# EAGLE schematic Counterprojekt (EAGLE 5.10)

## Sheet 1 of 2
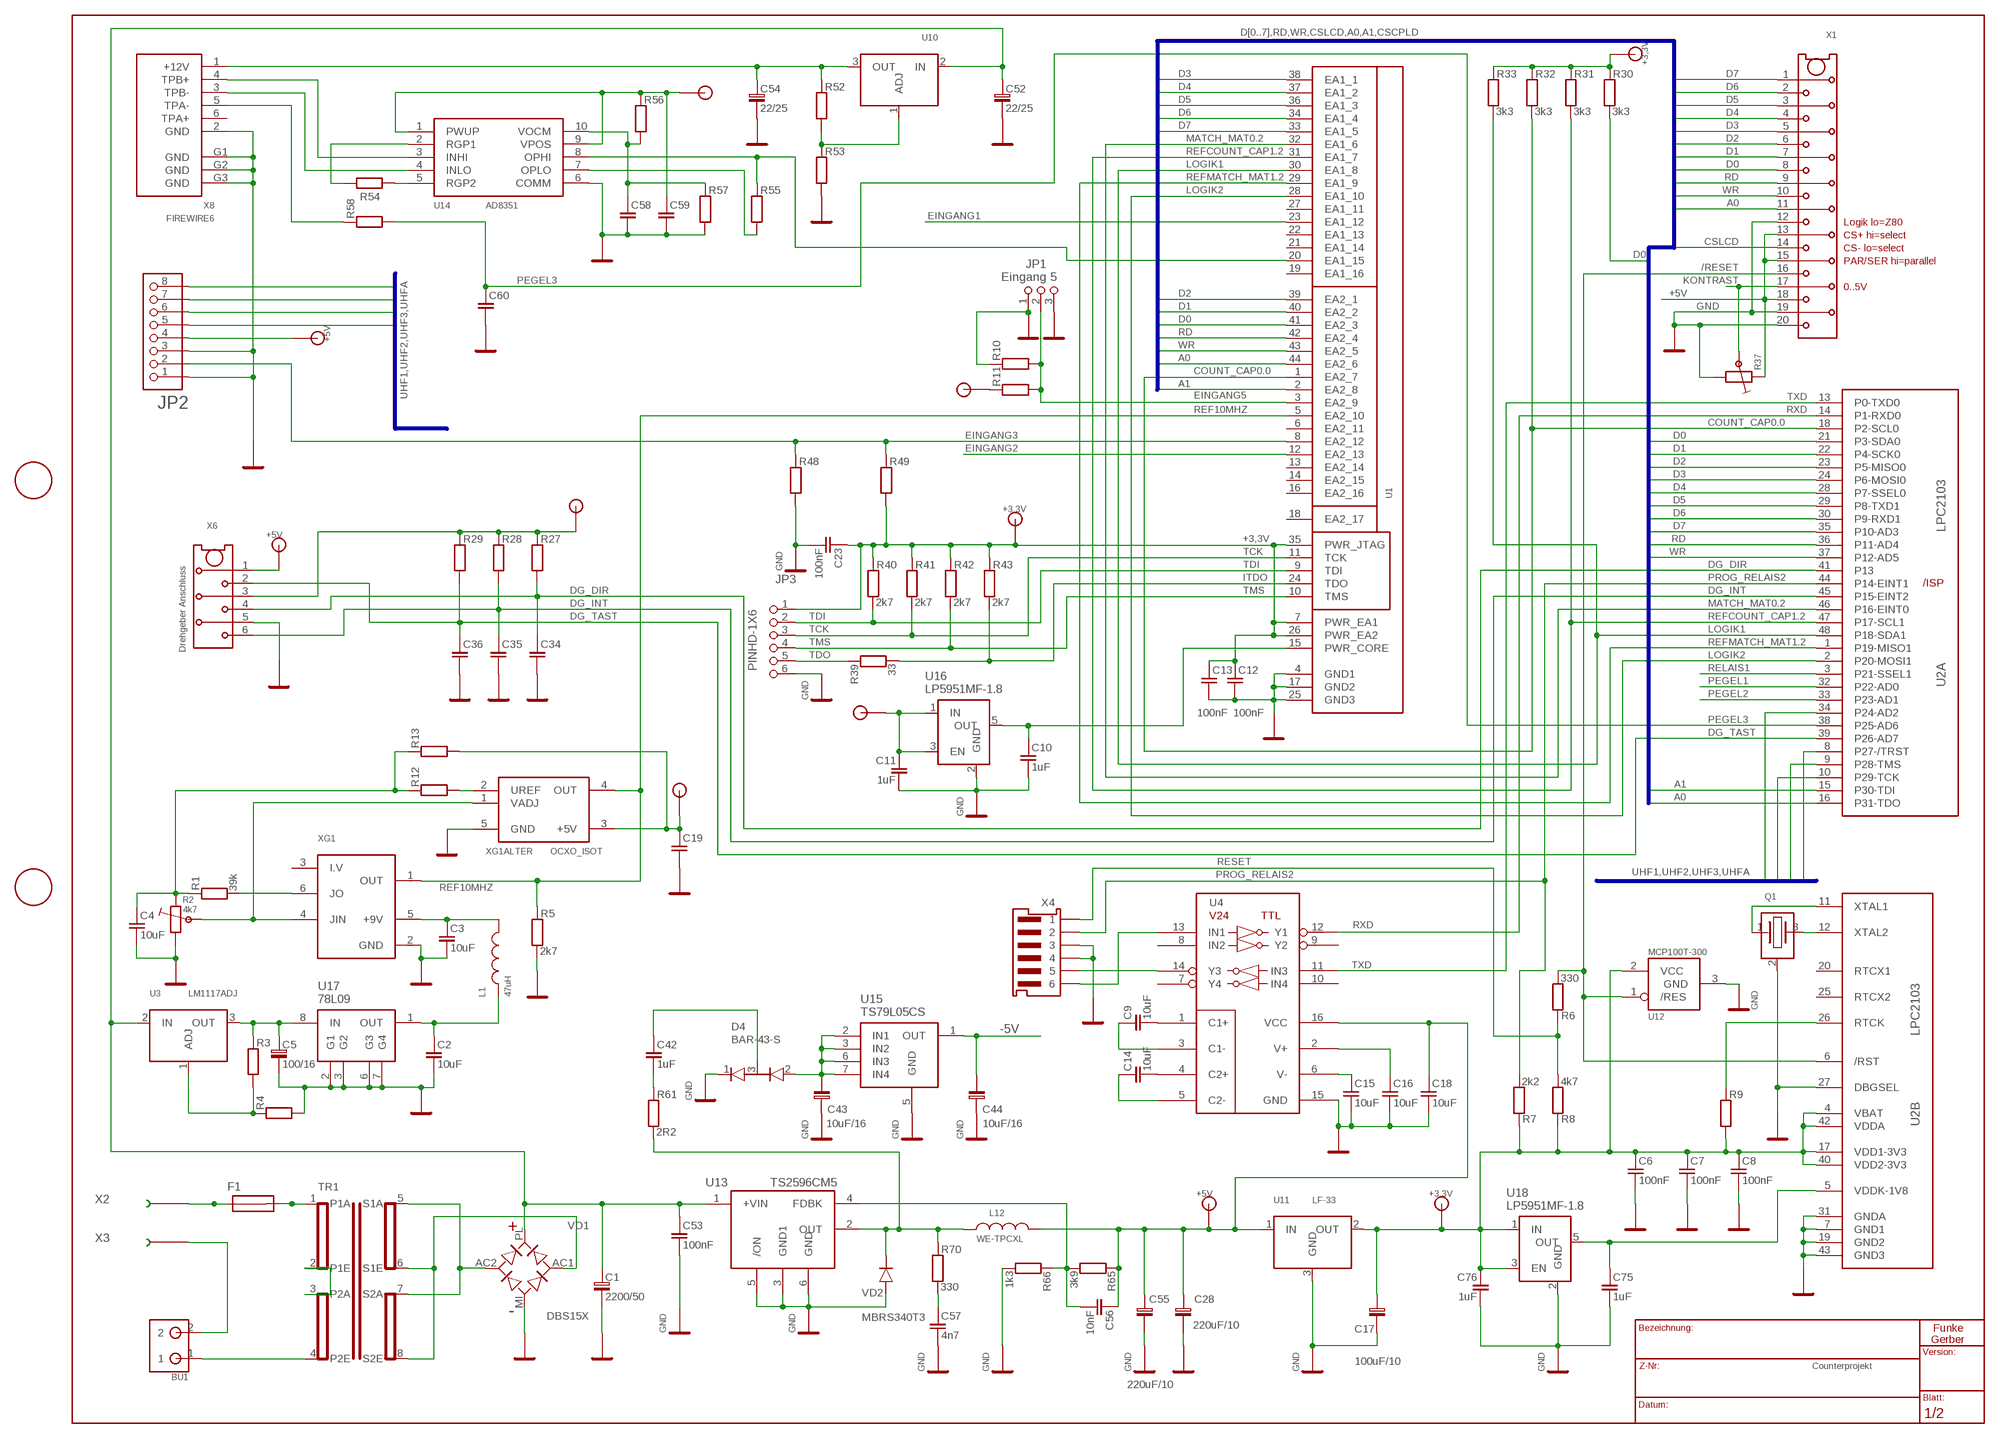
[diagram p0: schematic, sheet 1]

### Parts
BU1  NETZ_BU  [NETZ_BU]
C1  2200/50  [D25-RM10]
C2  10uF  SMD-1206  [SOT-1206]
C3  10uF  SMD-1206  [SOT-1206]
C4  10uF  SMD-1206  [SOT-1206]
C5  100/16  TAJ_D  [TAJ_D]
C6  100nF  SMD-0603  [SOT-0603]
C7  100nF  SMD-0603  [SOT-0603]
C8  100nF  SMD-0603  [SOT-0603]
C9  10uF  SMD-1206  [SOT-1206]
C10  1uF  SMD-0805@3  [SOT-0805@2]
C11  1uF  SMD-0805@3  [SOT-0805@2]
C12  100nF  SMD-0603  [SOT-0603]
C13  100nF  SMD-0603  [SOT-0603]
C14  10uF  SMD-1206  [SOT-1206]
C15  10uF  SMD-1206  [SOT-1206]
C16  10uF  SMD-1206  [SOT-1206]
C17  100uF/10  TAJ_D  [TAJ_D]
C18  10uF  SMD-1206  [SOT-1206]
C19  SMD-0805  [SOT-0805]
C23  100nF  SMD-1206@3  [SOT-0603]
C28  220uF/10  TAJ_D  [TAJ_D]
C34  SMD-0603  [SOT-0603]
C35  SMD-0603  [SOT-0603]
C36  SMD-0603  [SOT-0603]
C42  1uF  SMD-1206  [SOT-1206]
C43  10uF/16  TAJ_B  [TAJ_B]
C44  10uF/16  TAJ_B  [TAJ_B]
C52  22/25  TAJ_D  [TAJ_D]
C53  100nF  SMD-1206  [SOT-1206]
C54  22/25  TAJ_D  [TAJ_D]
C55  220uF/10  TAJ_D  [TAJ_D]
C56  10nF  SMD-0603  [SOT-0603]
C57  4n7  SMD-1206  [SOT-1206]
C58  SMD-0603  [SOT-0603]
C59  SMD-0603  [SOT-0603]
C60  SMD-0603  [SOT-0603]
C75  1uF  SMD-0805@3  [SOT-0805@2]
C76  1uF  SMD-0805@3  [SOT-0805@2]
D4  BAR-43-S  [SOT-23]
F1  FUS-HALT  [FUS-HALT]
JP1  Eingang 5  PINHD-1X3  [1X03]
JP2  PINHD-1X8  [1X08]
JP3  PINHD-1X6  [1X06]
L1  47uH  SMD-1210  [SMD-1210]
L12  WE-TPCXL  [WE-TPCXL]
Q1  ZTTCV  [ZTTCV]
R1  39k  SMD-0805  [SMD-0805]
R2  4k7  RFT10L  [RFT-LIEG]
R3  SMD-0805  [SMD-0805]
R4  SMD-0805  [SMD-0805]
R5  2k7  SMD-0805  [SMD-0805]
R6  330  SMD-0603  [SMD-0603]
R7  2k2  SMD-0603  [SMD-0603]
R8  4k7  SMD-0603  [SMD-0603]
R9  SMD-0603  [SMD-0603]
R10  SMD-0603  [SMD-0603]
R11  SMD-0603  [SMD-0603]
R12  SMD-0805  [SMD-0805]
R13  SMD-0805  [SMD-0805]
R27  SMD-0603  [SMD-0603]
R28  SMD-0603  [SMD-0603]
R29  SMD-0603  [SMD-0603]
R30  3k3  SMD-0603  [SMD-0603]
R31  3k3  SMD-0603  [SMD-0603]
R32  3k3  SMD-0603  [SMD-0603]
R33  3k3  SMD-0603  [SMD-0603]
R37  RFT10L  [RFT-LIEG]
R39  33  SMD-1206  [SMD-0603@1]
R40  2k7  SMD-1206  [SMD-0603@1]
R41  2k7  SMD-1206  [SMD-0603@1]
R42  2k7  SMD-1206  [SMD-0603@1]
R43  2k7  SMD-1206  [SMD-0603@1]
R48  SMD-0603  [SMD-0603]
R49  SMD-0603  [SMD-0603]
R52  SMD-0805  [SMD-0805]
R53  SMD-0805  [SMD-0805]
R54  SMD-0603  [SMD-0603]
R55  SMD-0603  [SMD-0603]
R56  SMD-0603  [SMD-0603]
R57  SMD-0603  [SMD-0603]
R58  SMD-0603  [SMD-0603]
R61  2R2  SMD-0805@3  [SMD-1206]
R65  3k9  SMD-0603@2  [SMD-0603@2]
R66  1k3  SMD-0603@2  [SMD-0603@2]
R70  330  SMD-1206  [SMD-1206]
TR1  HAHN-6VA  [HAHN-6VA]
U1  32A-VQ44  [VQ44]
U2  LPC2103  LPC210X  [LQFP48]
U3  LM1117ADJ  LM1117  [DPAK]
U4  MAX-232CWE  [SO-16W]
U10  LM1117  [DPAK]
U11  LF-33  LF-XXX  [DPAK]
U12  MCP100T-300  TC1275  [SOT23]
U13  TS2596CM5  [TO263-5L]
U14  AD8351  [RM-10]
U15  TS79L05CS  LM79SMDX  [SO-8]
U16  LP5951MF-1.8  LP5951MF  [SOT-23-5]
U17  78L09  LM78SMDX  [SO-8]
U18  LP5951MF-1.8  LP5951MF  [SOT-23-5]
VD1  DBS15X  [DBS15X]
VD2  MBRS340T3  [SMC]
X1  MICMATCH20  [MIMA20]
X2  LÖTÖSE  [LÖTÖSE]
X3  LÖTÖSE  [LÖTÖSE]
X4  Prog  LUMBG6  [LUMBG6]
X6  Drehgeber Anschluss  MICMATCH06  [MIMA6]
X8  FIREWIRE6  [IEEE1394-6V]
XG1  TXCO-4  [TXCO-4]
XG1ALTER  OCXO_ISOT  [OCXO_ISOT]

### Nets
+3,3V: C6.2 C7.2 C8.2 C11.2 C12.2 C13.2 C17.1 C23.2 C76.2 JP3.1 R7.2 R8.2 R9.1 R11.2 R27.2 R28.2 R29.2 R30.2 R31.2 R32.2 R33.2 R40.2 R41.2 R42.2 R43.2 R49.1 U1.7(PWR_EA1) U1.26(PWR_EA2) U1.35(PWR_JTAG) U2.4(B:VBAT) U2.17(B:VDD1-3V3) U2.40(B:VDD2-3V3) U2.42(B:VDDA) U11.2(OUT) U12.2(VCC) U16.1(IN) U16.3(EN) U18.1(IN) U18.3(EN) X6.3 ; also sheet 2
+5V: C18.2 C19.2 C28.1 C55.1 C56.2 C59.2 JP2.4 L12.2 R13.1 R37.2 R56.2 R65.2 U4.16(VCC) U11.1(IN) U14.1(PWUP) U14.9(VPOS) X1.13 X1.15 X1.18 X6.1 XG1ALTER.3(+5V) ; also sheet 2
+12EXT: C54.1 R52.2 U10.3(OUT) X8.1(+12V)
+12V: C1.1 C52.1 C53.2 U3.2(IN) U10.2(IN) U13.1(+VIN) VD1.PL
-5V: C44.2 U15.1(OUT) ; also sheet 2
/RESET: R6.1 U2.6(B:/RST) U12.1(/RES) X1.16
A0: U1.44(EA2_6) U2.16(A:P31-TDO) X1.11
A1: U1.2(EA2_8) U2.15(A:P30-TDI)
COUNT_CAP0.0: R32.1 U1.1(EA2_7) U2.18(A:P2-SCL0)
CSLCD: X1.14
D0: R30.1 U1.41(EA2_3) U2.21(A:P3-SDA0) X1.8
D1: U1.40(EA2_2) U2.22(A:P4-SCK0) X1.7
D2: U1.39(EA2_1) U2.23(A:P5-MISO0) X1.6
D3: U1.38(EA1_1) U2.24(A:P6-MOSI0) X1.5
D4: U1.37(EA1_2) U2.28(A:P7-SSEL0) X1.4
D5: U1.36(EA1_3) U2.29(A:P8-TXD1) X1.3
D6: U1.34(EA1_4) U2.30(A:P9-RXD1) X1.2
D7: U1.33(EA1_5) U2.35(A:P10-AD3) X1.1
DG_DIR: C34.2 R27.1 U2.41(A:P13) X6.4
DG_INT: C35.2 R28.1 U2.45(A:P15-EINT2) X6.6
DG_TAST: C36.2 R29.1 U2.39(A:P26-AD7) X6.2
EINGANG1: U1.23(EA1_12) ; also sheet 2
EINGANG2: U1.12(EA2_13) ; also sheet 2
EINGANG3: JP2.2 R48.2 R49.2 U1.8(EA2_12)
EINGANG5: JP1.2 R10.1 R11.1 U1.3(EA2_9)
GND: C1.2 C2.1 C3.1 C4.1 C5.2 C6.1 C7.1 C8.1 C10.1 C11.1 C12.1 C13.1 C15.1 C16.1 C17.2 C18.1 C19.1 C23.1 C28.2 C34.1 C35.1 C36.1 C43.1 C44.1 C52.2 C53.1 C54.2 C55.2 C57.1 C58.1 C59.1 C60.1 C75.1 C76.1 D4.1(K) JP1.1 JP1.3 JP2.1 JP2.3 JP3.6 Q1.2 R2.1 R4.1 R5.1 R10.2 R37.1 R48.1 R53.1 R57.1 R66.1 U1.4(GND1) U1.17(GND2) U1.25(GND3) U2.7(B:GND1) U2.19(B:GND2) U2.27(B:DBGSEL) U2.31(B:GNDA) U2.43(B:GND3) U4.15(GND) U11.3(GND) U12.3(GND) U13.3(GND1) U13.5(/ON) U13.6(GND) U14.6(COMM) U15.5(GND) U16.2(GND) U17.2(G1) U17.3(G2) U17.6(G3) U17.7(G4) U18.2(GND) VD1.MI VD2.A X1.12 X1.19 X1.20 X4.3 X4.4 X6.5 X8.2(GND) X8.G1(GND) X8.G2(GND) X8.G3(GND) XG1.2(GND) XG1ALTER.5(GND) ; also sheet 2
ITDO: R39.1 R43.1 U1.24(TDO)
KONTRAST: R37.3 X1.17
LOGIK1: R33.1 U1.30(EA1_8) U2.48(A:P18-SDA1)
LOGIK2: U1.28(EA1_10) U2.2(A:P20-MOSI1)
MATCH_MAT0.2: U1.32(EA1_6) U2.46(A:P16-EINT0)
N$1: TR1.2(P1E) TR1.3(P2A)
N$2: F1.2 F1.2A TR1.1(P1A)
N$3: F1.1 F1.1A X2.1
N$4: BU1.2 X3.1
N$5: BU1.1 TR1.4(P2E)
N$6: TR1.5(S1A) TR1.7(S2A) VD1.AC2
N$7: TR1.6(S1E) TR1.8(S2E) VD1.AC1
N$8: R9.2 U2.26(B:RTCK)
N$9: C2.2 L1.1 U17.1(OUT)
N$10: C3.2 L1.2 XG1.5(+9V)
N$11: R1.1 XG1.6(JO)
N$12: C4.2 R1.2 R2.2 R12.2 R13.2
N$13: R2.3 XG1.4(JIN) XG1ALTER.1(VADJ)
N$14: R3.1 R4.2 U3.1(ADJ)
N$15: Q1.3 U2.12(B:XTAL2)
N$16: Q1.1 U2.11(B:XTAL1)
N$17: C10.2 U1.15(PWR_CORE) U16.5(OUT)
N$18: C9.1 U4.1(C1+)
N$19: C14.1 U4.4(C2+)
N$20: C15.2 U4.6(V-)
N$21: C16.2 U4.2(V+)
N$22: U4.14(Y3) X4.5
N$23: C9.2 U4.3(C1-)
N$24: C14.2 U4.5(C2-)
N$25: U4.13(IN1) X4.6
N$28: R12.1 XG1ALTER.2(UREF)
N$47: L12.1 R61.1 R70.2 U13.2(OUT) VD2.K
N$57: C42.2 D4.3(KA)
N$58: C43.2 D4.2(A) U15.2(IN1) U15.3(IN2) U15.6(IN3) U15.7(IN4)
N$59: C42.1 R61.2
N$69: R52.1 R53.2 U10.1(ADJ)
N$70: U14.3(INHI) X8.4(TPB+)
N$71: U14.4(INLO) X8.3(TPB-)
N$72: R54.1 U14.5(RGP2)
N$73: R54.2 U14.2(RGP1)
N$74: C57.2 R70.1
N$75: C56.1 R65.1 R66.2 U13.4(FDBK)
N$77: R55.1 U14.7(OPLO)
N$78: C58.2 R56.1 R57.2 U14.10(VOCM)
N$79: R55.2 U1.20(EA1_15) U14.8(OPHI)
N$80: R58.2 X8.5(TPA-)
OUT: C5.1 R3.2 U3.3(OUT) U17.8(IN)
PEGEL1: U2.32(A:P22-AD0) ; also sheet 2
PEGEL2: U2.33(A:P23-AD1) ; also sheet 2
PEGEL3: C60.2 R58.1 U2.38(A:P25-AD6)
PROG_RELAIS2: R7.1 U2.44(A:P14-EINT1) X4.2 ; also sheet 2
RD: U1.42(EA2_4) U2.36(A:P11-AD4) X1.9
REF10MHZ: R5.2 U1.5(EA2_10) XG1.1(OUT) XG1ALTER.4(OUT)
REFCOUNT_CAP1.2: R31.1 U1.31(EA1_7) U2.47(A:P17-SCL1)
REFMATCH_MAT1.2: U1.29(EA1_9) U2.1(A:P19-MISO1)
RELAIS1: U2.3(A:P21-SSEL1) ; also sheet 2
RESET: R6.2 R8.1 X4.1
RXD: U2.14(A:P1-RXD0) U4.12(Y1)
TCK: JP3.3 R41.1 U1.11(TCK)
TDI: JP3.2 R40.1 U1.9(TDI)
TDO: JP3.5 R39.2
TMS: JP3.4 R42.1 U1.10(TMS)
TXD: U2.13(A:P0-TXD0) U4.11(IN3)
UHF1: JP2.5 U2.8(A:P27-/TRST)
UHF2: JP2.6 U2.9(A:P28-TMS)
UHF3: JP2.7 U2.10(A:P29-TCK)
UHFA: JP2.8 U2.34(A:P24-AD2)
VCORE1.8: C75.2 U2.5(B:VDDK-1V8) U18.5(OUT)
WR: U1.43(EA2_5) U2.37(A:P12-AD5) X1.10
Unconnected: U1.6(EA2_11) U1.13(EA2_14) U1.14(EA2_15) U1.16(EA2_16) U1.18(EA2_17) U1.19(EA1_16) U1.21(EA1_14) U1.22(EA1_13) U1.27(EA1_11) U2.20(B:RTCX1) U2.25(B:RTCX2) U4.7(Y4) U4.8(IN2) U4.9(Y2) U4.10(IN4) X8.6(TPA+) XG1.3(I.V)

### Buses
D[0..7],RD,WR,CSLCD,A0,A1,CSCPLD
UHF1,UHF2,UHF3,UHFA

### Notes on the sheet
- Logik lo=Z80
- CS+ hi=select
- CS- lo=select
- PAR/SER hi=parallel
- 0..5V

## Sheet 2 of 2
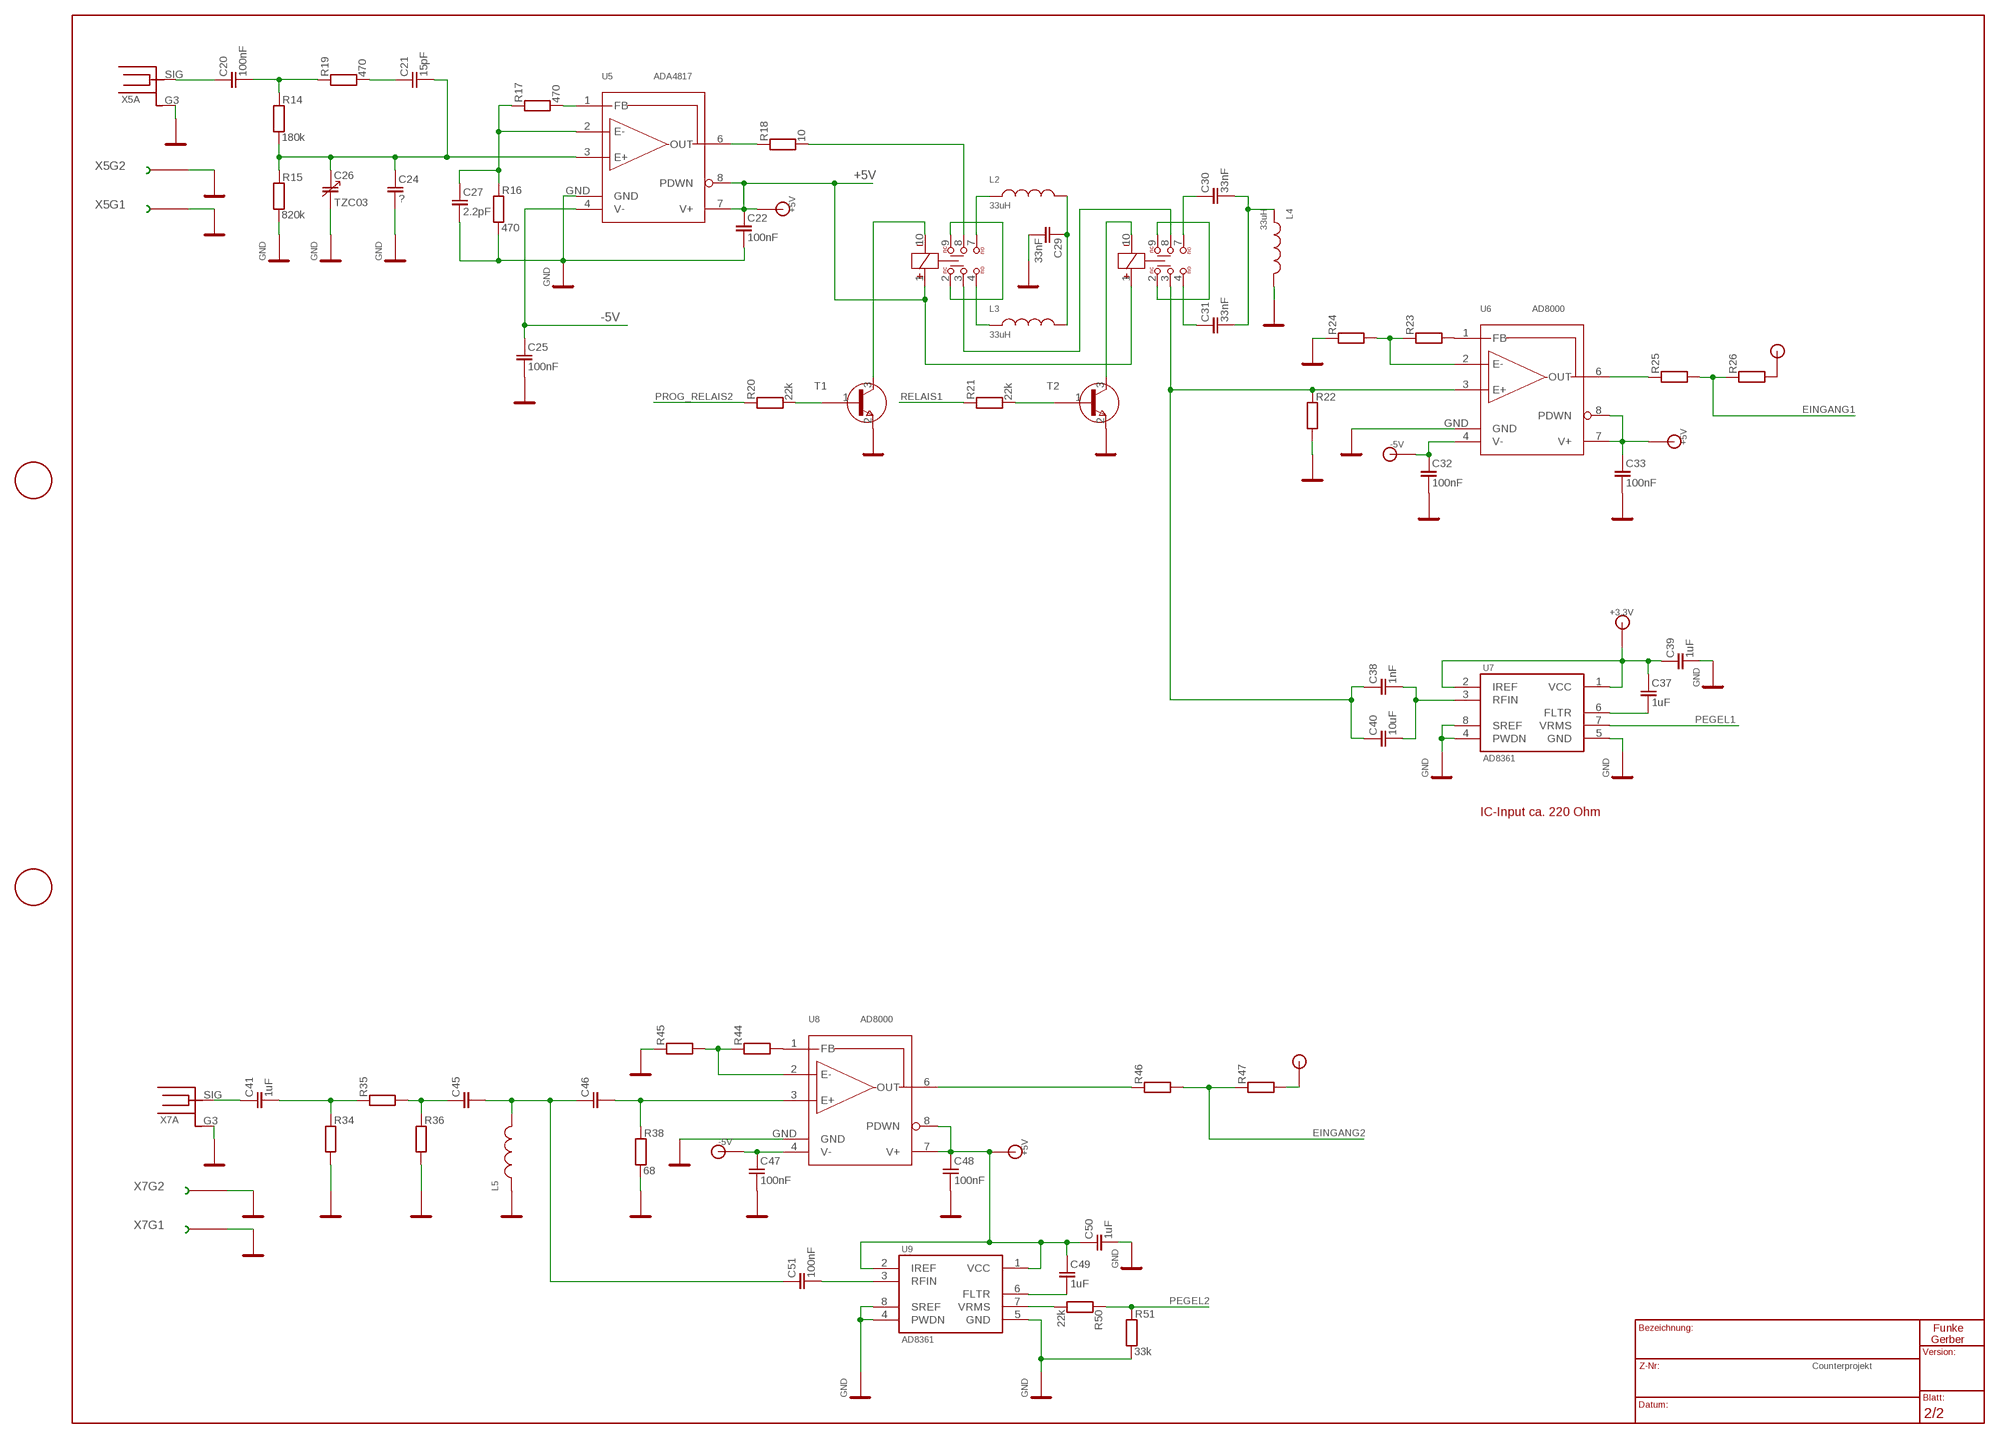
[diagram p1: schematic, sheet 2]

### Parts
C20  100nF  SMD-0603  [SOT-0603]
C21  15pF  SMD-0603  [SOT-0603]
C22  100nF  SMD-0603  [SOT-0603]
C24  ?  SMD-0603  [SOT-0603]
C25  100nF  SMD-0603  [SOT-0603]
C26  TZC03  [TZC03]
C27  2.2pF  SMD-0603  [SOT-0603]
C29  33nF  SMD-1206  [SOT-1206]
C30  33nF  SMD-1206  [SOT-1206]
C31  33nF  SMD-1206  [SOT-1206]
C32  100nF  SMD-0603  [SOT-0603]
C33  100nF  SMD-0603  [SOT-0603]
C37  1uF  SMD-0805  [SOT-0805]
C38  1nF  SMD-0603  [SOT-0603]
C39  1uF  SMD-0805  [SOT-0805]
C40  10uF  SMD-1206  [SOT-1206]
C41  1uF  SMD-0805  [SOT-0805]
C45  SMD-0805  [SOT-0805]
C46  SMD-0805  [SOT-0805]
C47  100nF  SMD-0603  [SOT-0603]
C48  100nF  SMD-0603  [SOT-0603]
C49  1uF  SMD-0805  [SOT-0805]
C50  1uF  SMD-0805  [SOT-0805]
C51  100nF  SMD-0603  [SOT-0603]
L2  33uH  SMD-1210  [SMD-1210]
L3  33uH  SMD-1210  [SMD-1210]
L4  33uH  SMD-1210  [SMD-1210]
L5  SMD-1210  [SMD-1210]
R14  180k  SMD-0603  [SMD-0603]
R15  820k  SMD-0603  [SMD-0603]
R16  470  SMD-0603  [SMD-0603]
R17  470  SMD-0603  [SMD-0603]
R18  10  SMD-0603  [SMD-0603]
R19  470  SMD-0603  [SMD-0603]
R20  22k  SMD-0805  [SMD-0805]
R21  22k  SMD-0805  [SMD-0805]
R22  SMD-0603  [SMD-0603]
R23  SMD-0603  [SMD-0603]
R24  SMD-0603  [SMD-0603]
R25  SMD-0603  [SMD-0603]
R26  SMD-0603  [SMD-0603]
R34  SMD-0805  [SMD-0805]
R35  SMD-0805  [SMD-0805]
R36  SMD-0805  [SMD-0805]
R38  68  SMD-0603  [SMD-0603]
R44  SMD-0603  [SMD-0603]
R45  SMD-0603  [SMD-0603]
R46  SMD-0603  [SMD-0603]
R47  SMD-0603  [SMD-0603]
R50  22k  SMD-0603  [SMD-0603]
R51  33k  SMD-0603  [SMD-0603]
REL1  TQ-RELAIS  [TQ-RELAI]
REL2  TQ-RELAIS  [TQ-RELAI]
T1  BC817-40  [SOT-23]
T2  BC817-40  [SOT-23]
U5  ADA4817  AD8000  [SO-8EXP]
U6  AD8000  [SO-8EXP]
U7  AD8361  [U-SOIC8]
U8  AD8000  [SO-8EXP]
U9  AD8361  [U-SOIC8]
X5  BNC  [BNC]
X7  BNC  [BNC]

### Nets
+3,3V: C37.2 C39.2 R26.1 R47.1 U7.1(VCC) U7.2(IREF) ; also sheet 1
+5V: C22.2 C33.2 C48.2 C49.2 C50.2 REL1.1(L+) REL2.1(L+) U5.7(V+) U5.8(PDWN) U6.7(V+) U6.8(PDWN) U8.7(V+) U8.8(PDWN) U9.1(VCC) U9.2(IREF) ; also sheet 1
-5V: C25.2 C32.2 C47.2 U5.4(V-) U6.4(V-) U8.4(V-) ; also sheet 1
EINGANG1: R25.1 R26.2 ; also sheet 1
EINGANG2: R46.1 R47.2 ; also sheet 1
GND: C22.1 C24.1 C25.1 C26.2 C27.1 C29.1 C32.1 C33.1 C39.1 C47.1 C48.1 C50.1 L4.2 L5.1 R15.1 R16.1 R22.1 R24.2 R34.1 R36.1 R38.1 R45.2 R51.1 T1.2(E) T2.2(E) U5.GND U6.GND U7.4(PWDN) U7.5(GND) U7.8(SREF) U8.GND U9.4(PWDN) U9.5(GND) U9.8(SREF) X5.G1 X5.G2 X5.G3 X7.G1 X7.G2 X7.G3 ; also sheet 1
N$26: C37.1 U7.6(FLTR)
N$27: C20.2 X5.SIG
N$29: C20.1 R14.2 R19.2
N$30: C21.1 C24.2 C26.1 R14.1 R15.2 U5.3(E+)
N$31: C21.2 R19.1
N$32: C27.2 R16.2 R17.2 U5.2(E-)
N$33: R17.1 U5.1(FB)
N$34: R18.2 U5.6(OUT)
N$35: R18.1 REL1.8(M2)
N$36: REL1.2(NC1) REL1.9(NC2)
N$37: REL1.3(M1) REL2.8(M2)
N$38: REL2.2(NC1) REL2.9(NC2)
N$39: L2.1 REL1.7(NO2)
N$40: C29.2 L2.2 L3.2
N$41: L3.1 REL1.4(NO1)
N$42: C30.2 REL2.7(NO2)
N$43: C31.2 REL2.4(NO1)
N$44: C30.1 C31.1 L4.1
N$45: R20.1 T1.1(B)
N$46: R21.1 T2.1(B)
N$48: REL2.10(L-) T2.3(C)
N$49: REL1.10(L-) T1.3(C)
N$50: C38.2 C40.2 R22.2 REL2.3(M1) U6.3(E+)
N$51: R23.1 U6.1(FB)
N$52: R23.2 R24.1 U6.2(E-)
N$53: R25.2 U6.6(OUT)
N$54: C38.1 C40.1 U7.3(RFIN)
N$55: C41.2 X7.SIG
N$56: C41.1 R34.2 R35.2
N$60: C45.2 R35.1 R36.2
N$61: C45.1 C46.2 C51.2 L5.2
N$62: C46.1 R38.2 U8.3(E+)
N$63: R44.1 U8.1(FB)
N$64: R44.2 R45.1 U8.2(E-)
N$65: R46.2 U8.6(OUT)
N$66: R50.1 U9.7(VRMS)
N$67: C49.1 U9.6(FLTR)
N$68: C51.1 U9.3(RFIN)
PEGEL1: U7.7(VRMS) ; also sheet 1
PEGEL2: R50.2 R51.2 ; also sheet 1
PROG_RELAIS2: R20.2 ; also sheet 1
RELAIS1: R21.2 ; also sheet 1

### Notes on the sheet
- IC-Input ca. 220 Ohm

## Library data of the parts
BU1 = HAMRAD:NETZ_BU
C1 = ELKO_ST:2200/50
C2-C4 C9 C14-C16 C18 C29-C31 C40 C42 C53 C57 = C_KERAM:SMD-1206
C5 C17 C28 C52 C54 C55 = ELKO_LG:TAJ_D
C6-C8 C12 C13 C20-C22 C24 C25 C27 C32-C36 C38 C47 C48 C51 C56 C58-C60 = C_KERAM:SMD-0603
C10 C11 C75 C76 = C_KERAM:SMD-0805@3
C19 C37 C39 C41 C45 C46 C49 C50 = C_KERAM:SMD-0805
C23 = C_KERAM:SMD-1206@3
C26 = C_KERAM:TZC03: SMD-Trimmer 1.4-3, 2-6, 3-10, 5-20, 6-30
C43 C44 = ELKO_LG@2:TAJ_B
D4 = DIODEN@2:BAR-43-S
F1 = Z_SPECIA:FUS-HALT
JP1 = PINHD-Q:PINHD-1X3
JP2 = PINHEAD:PINHD-1X8
JP3 = PINHD-Q:PINHD-1X6
L1-L5 = L:SMD-1210
L12 = L:WE-TPCXL
Q1 = Z_SPECIA:ZTTCV
R1 R3-R5 R12 R13 R20 R21 R34-R36 R52 R53 = R:SMD-0805
R2 R37 = R:RFT10L
R6 = R@2:SMD-0603
R7-R11 R14-R19 R22-R33 R38 R44-R51 R54-R58 = R:SMD-0603
R39-R43 = R@2:SMD-1206
R61 = R@2:SMD-0805@3
R65 R66 = R:SMD-0603@2
R70 = R:SMD-1206
REL1 REL2 = HAMRAD:TQ-RELAIS
T1 T2 = TR_NPN:BC817-40
TR1 = L:HAHN-6VA
U1 = XILINX-Coolrunner2:32A-VQ44
U2 = PHILIPS:LPC210X
U3 U10 = SGS:LM1117
U4 = MAXIM:MAX-232CWE
U5 U6 U8 = ANALOG_D:AD8000
U7 U9 = ANALOG_D:AD8361
U11 = SGS:LF-XXX
U12 = MIC_CHIP:TC1275
U13 = TSC:TS2596CM5
U14 = ANALOG_D:AD8351
U15 = NSC2:LM79SMDX
U16 U18 = NSC:LP5951MF
U17 = NSC:LM78SMDX
VD1 = DIODEN:DBS15X
VD2 = DIODEN:MBRS340T3
X1 = TYCO:MICMATCH20
X2 X3 = Z_CONNEC:LÖTÖSE
X4 = Z_CONNEC:LUMBG6
X5 X7 = Z_CONNEC:BNC
X6 = TYCO:MICMATCH06
X8 = Z_CONNEC:FIREWIRE6
XG1 = URKRAM:TXCO-4
XG1ALTER = Z_SPECIA:OCXO_ISOT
